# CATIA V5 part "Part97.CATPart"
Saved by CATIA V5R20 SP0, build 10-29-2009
Part number: IA 3217SF
Revision: ANY
Definition: UNKNOWN
Nomenclature: IA 3217SF
Source: Unknown
Bounding box of the stored display mesh (mm): x -1.6 to 1.6, y -8.75 to 8.2, z -1.6 to 1.6
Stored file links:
  C:\Users\Utente\Desktop\IO LAVORO\3D X SITO CF\CUMSA\3D files FA\FA 063205-20\Part97.CATPart

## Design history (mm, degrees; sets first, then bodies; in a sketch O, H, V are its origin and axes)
Body1 "Cortar-Extruir2" (main body)
  Solid1: solid without history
